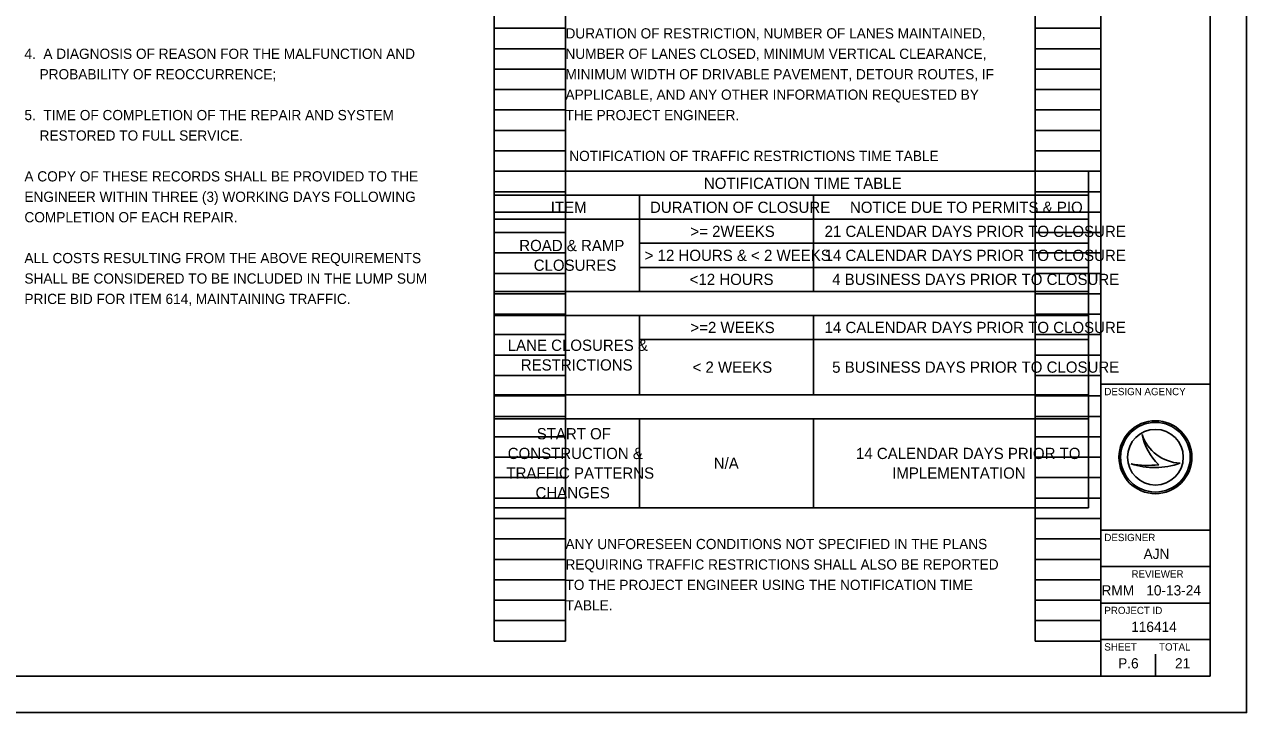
# Model space of a CAD drawing. Extents: x -6 to 34, y 0 to 22.
# Drawn here: x 17.24 to 34, y 0 to 9.43 of the extents above; entities that cross this region are included whole.
import ezdxf

# ---------------------------------------------------------------- set-up
doc = ezdxf.new("R2010")
doc.units = 0
for name, color, linetype in [('SH_Border', 7, 'Continuous'), ('SH_Cut_Line', 7, 'Continuous'), ('SH_Data', 7, 'Continuous'), ('SH_Text', 7, 'Continuous')]:
    doc.layers.add(name, color=color, linetype=linetype)

msp = doc.modelspace()

# ---------------------------------------------------------------- linework, layer by layer
at = {"layer": 'SH_Border'}
for p, q in [((32, 0.5), (32, 21.5)), ((32, 4.5), (33.5, 4.5)), ((32, 2.5), (33.5, 2.5)), ((32, 2), (33.5, 2)), ((32, 1.5), (33.5, 1.5)), ((32, 1), (33.5, 1))]:
    msp.add_line(p, q, dxfattribs=at)
msp.add_lwpolyline([(1.5, 21.5), (33.5, 21.5), (33.5, 0.5), (1.5, 0.5)], close=True, dxfattribs=at)
at = {"layer": 'SH_Cut_Line'}
msp.add_lwpolyline([(0, 0), (34, 0), (34, 22), (0, 22)], close=True, dxfattribs=at)
at = {"layer": 'SH_Data'}
for p, q in [((23.68, 0.98), (23.68, 21.14)), ((24.66, 0.98), (24.66, 21.14)), ((31.1, 0.98), (31.1, 21.14)), ((32, 0.98), (32, 21.14)), ((23.68, 9.38), (24.66, 9.38)), ((31.1, 9.38), (32, 9.38)), ((23.68, 9.1), (24.66, 9.1)), ((31.1, 9.1), (32, 9.1)), ((23.68, 8.82), (24.66, 8.82)), ((31.1, 8.82), (32, 8.82)), ((23.68, 8.54), (24.66, 8.54)), ((31.1, 8.54), (32, 8.54)), ((23.68, 8.26), (24.66, 8.26)), ((31.1, 8.26), (32, 8.26)), ((23.68, 7.98), (24.66, 7.98)), ((31.1, 7.98), (32, 7.98)), ((23.68, 7.7), (24.66, 7.7)), ((31.1, 7.7), (32, 7.7)), ((23.68, 7.42), (24.66, 7.42)), ((31.1, 7.42), (32, 7.42)), ((23.68, 7.14), (24.66, 7.14)), ((31.1, 7.14), (32, 7.14)), ((23.68, 6.86), (24.66, 6.86)), ((31.1, 6.86), (32, 6.86)), ((23.68, 6.58), (24.66, 6.58)), ((31.1, 6.58), (32, 6.58)), ((23.68, 6.3), (24.66, 6.3)), ((31.1, 6.3), (32, 6.3)), ((23.68, 6.02), (24.66, 6.02)), ((31.1, 6.02), (32, 6.02)), ((23.68, 5.74), (24.66, 5.74)), ((31.1, 5.74), (32, 5.74)), ((23.68, 5.46), (24.66, 5.46)), ((31.1, 5.46), (32, 5.46)), ((23.68, 5.18), (24.66, 5.18)), ((31.1, 5.18), (32, 5.18)), ((23.68, 4.9), (24.66, 4.9)), ((31.1, 4.9), (32, 4.9)), ((23.68, 4.62), (24.66, 4.62)), ((31.1, 4.62), (32, 4.62)), ((23.68, 4.34), (24.66, 4.34)), ((31.1, 4.34), (32, 4.34)), ((23.68, 4.06), (24.66, 4.06)), ((31.1, 4.06), (32, 4.06)), ((23.68, 3.78), (24.66, 3.78)), ((31.1, 3.78), (32, 3.78)), ((32.567, 3.81), (32.567, 3.81)), ((23.68, 3.5), (24.66, 3.5)), ((31.1, 3.5), (32, 3.5)), ((32.417, 3.41), (32.417, 3.41)), ((32.75, 3.5), (32.75, 3.5)), ((33.087, 3.419), (33.087, 3.419)), ((23.68, 3.22), (24.66, 3.22)), ((31.1, 3.22), (32, 3.22)), ((23.68, 2.94), (24.66, 2.94)), ((31.1, 2.94), (32, 2.94)), ((23.68, 2.66), (24.66, 2.66)), ((31.1, 2.66), (32, 2.66)), ((23.68, 2.38), (24.66, 2.38)), ((31.1, 2.38), (32, 2.38)), ((23.68, 2.1), (24.66, 2.1)), ((31.1, 2.1), (32, 2.1)), ((23.68, 1.82), (24.66, 1.82)), ((31.1, 1.82), (32, 1.82)), ((23.68, 1.54), (24.66, 1.54)), ((31.1, 1.54), (32, 1.54)), ((23.68, 1.26), (24.66, 1.26)), ((31.1, 1.26), (32, 1.26)), ((23.68, 0.98), (24.66, 0.98)), ((31.1, 0.98), (32, 0.98)), ((32.375, 0.675), (32.375, 0.675)), ((32.75, 0.5), (32.75, 0.8))]:
    msp.add_line(p, q, dxfattribs=at)
for radius in [0.5, 0.477, 0.477, 0.382]:
    msp.add_circle((32.75, 3.5), radius, dxfattribs=at)
for centre, radius, start, end in [((33.116, 3.998), 0.58, 198.9257, 198.9319), ((33.347, 3.97), 0.796, 191.6379, 191.6421), ((33.116, 3.998), 0.58, 198.9319, 267.1657), ((33.347, 3.97), 0.796, 191.6421, 226.0947), ((32.739, 4.37), 1.013, 251.4576, 290.0832), ((32.648, 4.654), 1.266, 259.4964, 259.4995), ((32.739, 4.37), 1.013, 251.4527, 251.4576), ((32.648, 4.654), 1.266, 259.4995, 276.6672)]:
    msp.add_arc(centre, radius, start, end, dxfattribs=at)
at = {"layer": 'SH_Text'}
for p, q in [((23.68, 7.42), (31.833, 7.42)), ((23.68, 7.42), (23.68, 2.808)), ((31.833, 7.42), (31.833, 2.808)), ((23.68, 7.091), (31.833, 7.091)), ((25.673, 7.091), (25.673, 5.773)), ((28.061, 7.091), (28.061, 5.773)), ((23.68, 6.761), (31.833, 6.761)), ((25.673, 6.432), (31.833, 6.432)), ((25.673, 6.102), (31.833, 6.102)), ((23.68, 5.773), (31.833, 5.773)), ((23.68, 5.444), (31.833, 5.444)), ((25.673, 5.444), (25.673, 4.356)), ((28.061, 5.444), (28.061, 4.356)), ((25.673, 5.114), (31.833, 5.114)), ((23.68, 4.356), (31.833, 4.356)), ((23.68, 4.027), (31.833, 4.027)), ((25.673, 4.027), (25.673, 2.808)), ((28.061, 4.027), (28.061, 2.808)), ((23.68, 2.808), (31.833, 2.808))]:
    msp.add_line(p, q, dxfattribs=at)

# ---------------------------------------------------------------- texts
at = {"layer": 'SH_Data'}
for s, height, p in [('DESIGN AGENCY', 0.1, (32.05, 4.35)), ('DESIGNER', 0.1, (32.05, 2.35)), ('AJN', 0.14, (32.588, 2.105)), ('REVIEWER', 0.1, (32.422, 1.85)), ('RMM', 0.14, (32.011, 1.605)), ('10-13-24', 0.14, (32.625, 1.605)), ('PROJECT ID', 0.1, (32.05, 1.35)), ('116414', 0.14, (32.418, 1.105)), ('SHEET', 0.1, (32.05, 0.85)), ('TOTAL', 0.1, (32.8, 0.85)), ('P.6', 0.14, (32.239, 0.605)), ('21', 0.14, (33.019, 0.605))]:
    msp.add_text(s, height=height, dxfattribs=at).set_placement(p)
at = {"layer": 'SH_Text'}
for s, height, p in [('DURATION OF RESTRICTION, NUMBER OF LANES MAINTAINED,', 0.14, (24.66, 9.24)), ('4.  A DIAGNOSIS OF REASON FOR THE MALFUNCTION AND', 0.14, (17.24, 8.96)), ('NUMBER OF LANES CLOSED, MINIMUM VERTICAL CLEARANCE,', 0.14, (24.66, 8.96)), ('    PROBABILITY OF REOCCURRENCE;', 0.14, (17.24, 8.68)), ('MINIMUM WIDTH OF DRIVABLE PAVEMENT, DETOUR ROUTES, IF', 0.14, (24.66, 8.68)), ('APPLICABLE, AND ANY OTHER INFORMATION REQUESTED BY', 0.14, (24.66, 8.4)), ('5.  TIME OF COMPLETION OF THE REPAIR AND SYSTEM', 0.14, (17.24, 8.12)), ('THE PROJECT ENGINEER.', 0.14, (24.66, 8.12)), ('    RESTORED TO FULL SERVICE.', 0.14, (17.24, 7.84)), (' NOTIFICATION OF TRAFFIC RESTRICTIONS TIME TABLE', 0.14, (24.66, 7.56)), ('A COPY OF THESE RECORDS SHALL BE PROVIDED TO THE', 0.14, (17.24, 7.28)), ('NOTIFICATION TIME TABLE', 0.154, (26.558, 7.178)), ('ENGINEER WITHIN THREE (3) WORKING DAYS FOLLOWING', 0.14, (17.24, 7)), ('ITEM', 0.154, (24.458, 6.849)), ('DURATION OF CLOSURE', 0.154, (25.819, 6.849)), ('NOTICE DUE TO PERMITS & PIO', 0.154, (28.561, 6.849)), ('COMPLETION OF EACH REPAIR.', 0.14, (17.24, 6.72)), ('>= 2WEEKS', 0.154, (26.373, 6.519)), ('21 CALENDAR DAYS PRIOR TO CLOSURE', 0.154, (28.213, 6.519)), ('ROAD & RAMP ', 0.154, (24.026, 6.325)), ('ALL COSTS RESULTING FROM THE ABOVE REQUIREMENTS', 0.14, (17.24, 6.16)), ('CLOSURES', 0.154, (24.224, 6.055)), ('> 12 HOURS & < 2 WEEKS', 0.154, (25.746, 6.19)), ('14 CALENDAR DAYS PRIOR TO CLOSURE', 0.154, (28.213, 6.19)), ('SHALL BE CONSIDERED TO BE INCLUDED IN THE LUMP SUM', 0.14, (17.24, 5.88)), ('<12 HOURS', 0.154, (26.363, 5.861)), ('4 BUSINESS DAYS PRIOR TO CLOSURE', 0.154, (28.317, 5.861)), ('PRICE BID FOR ITEM 614, MAINTAINING TRAFFIC.', 0.14, (17.24, 5.6)), ('>=2 WEEKS', 0.154, (26.373, 5.202)), ('14 CALENDAR DAYS PRIOR TO CLOSURE', 0.154, (28.213, 5.202)), ('LANE CLOSURES & ', 0.154, (23.868, 4.958)), ('RESTRICTIONS', 0.154, (24.047, 4.688)), ('< 2 WEEKS', 0.154, (26.402, 4.658)), ('5 BUSINESS DAYS PRIOR TO CLOSURE', 0.154, (28.317, 4.658)), ('START OF ', 0.154, (24.265, 3.745)), ('CONSTRUCTION & ', 0.154, (23.868, 3.475)), ('14 CALENDAR DAYS PRIOR TO ', 0.154, (28.644, 3.475)), ('TRAFFIC PATTERNS ', 0.154, (23.85, 3.206)), ('N/A', 0.154, (26.693, 3.341)), ('IMPLEMENTATION', 0.154, (29.14, 3.206)), ('CHANGES', 0.154, (24.249, 2.936)), ('ANY UNFORESEEN CONDITIONS NOT SPECIFIED IN THE PLANS', 0.14, (24.66, 2.24)), ('REQUIRING TRAFFIC RESTRICTIONS SHALL ALSO BE REPORTED', 0.14, (24.66, 1.96)), ('TO THE PROJECT ENGINEER USING THE NOTIFICATION TIME', 0.14, (24.66, 1.68)), ('TABLE.', 0.14, (24.66, 1.4))]:
    msp.add_text(s, height=height, dxfattribs=at).set_placement(p)

doc.saveas('drawing.dxf')
